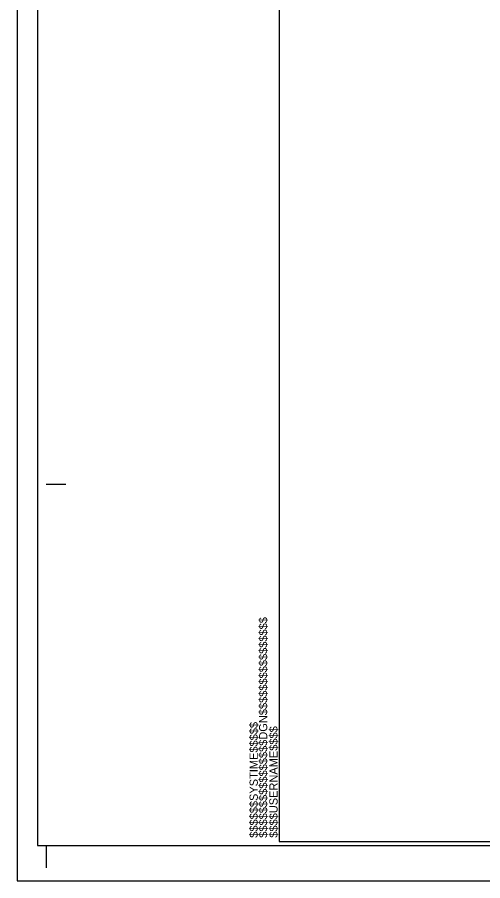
# Model space of a CAD drawing. Extents: x 1542177 to 1542464, y 45134 to 45344.
# Drawn here: x 1542226.01 to 1542249.74, y 45240.62 to 45284.62 of the extents above; entities that cross this region are included whole.
import ezdxf

# ---------------------------------------------------------------- set-up
doc = ezdxf.new("R2010")
doc.units = 0
for name, color, linetype in [('Default', 7, 'Continuous'), ('Sheet Cutting Line CELL', 7, 'Continuous'), ('Sheet Plot Border Inside CELL', 7, 'Continuous'), ('Sheet Plot Border Outside CELL', 7, 'Continuous'), ('Sheet Typical CELL', 7, 'Continuous')]:
    doc.layers.add(name, color=color, linetype=linetype)

# ---------------------------------------------------------------- blocks, each defined once
blk = doc.blocks.new('POINT_DISPLAY')
at = {"layer": 'Default'}
blk.add_line((0, 0), (0, 0), dxfattribs=at)

msp = doc.modelspace()

# ---------------------------------------------------------------- linework, layer by layer
at = {"layer": 'Sheet Cutting Line CELL'}
for p, q in [((1542226.007, 45328.616), (1542226.007, 45240.616)), ((1542226.007, 45240.616), (1542360.727, 45240.616))]:
    msp.add_line(p, q, dxfattribs=at)
at = {"layer": 'Sheet Plot Border Inside CELL'}
msp.add_lwpolyline([(1542360.367, 45326.82), (1542227.047, 45326.82), (1542227.047, 45242.412), (1542360.367, 45242.412)], close=True, dxfattribs=at)
at = {"layer": 'Sheet Plot Border Outside CELL'}
for points in [[(1542360.727, 45328.616), (1542226.007, 45328.616), (1542226.007, 45240.616), (1542360.727, 45240.616)], [(1542360.727, 45328.615), (1542226.007, 45328.615), (1542226.007, 45240.616), (1542360.727, 45240.616)]]:
    msp.add_lwpolyline(points, close=True, dxfattribs=at)
at = {"layer": 'Sheet Typical CELL'}
for p, q in [((1542227.487, 45260.816), (1542228.487, 45260.816)), ((1542239.367, 45242.616), (1542239.367, 45242.616)), ((1542239.367, 45242.616), (1542239.367, 45242.616)), ((1542239.367, 45242.616), (1542239.367, 45242.616)), ((1542239.367, 45242.616), (1542239.367, 45242.616)), ((1542239.367, 45242.616), (1542239.367, 45242.616)), ((1542239.367, 45242.616), (1542239.367, 45242.616)), ((1542227.487, 45242.412), (1542227.487, 45241.267))]:
    msp.add_line(p, q, dxfattribs=at)
msp.add_lwpolyline([(1542359.367, 45326.616), (1542239.367, 45326.616), (1542239.367, 45242.616), (1542359.367, 45242.616)], close=True, dxfattribs=at)
msp.add_lwpolyline([(1542242.367, 45242.616), (1542242.367, 45242.616)], dxfattribs=at)

# ---------------------------------------------------------------- block references
at = {"layer": 'Default', "xscale": 1.3123333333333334, "yscale": 1.3123333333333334}
msp.add_blockref('POINT_DISPLAY', (1542239.367, 45242.616), dxfattribs=at)
msp.add_blockref('POINT_DISPLAY', (1542239.367, 45242.616), dxfattribs=at)
msp.add_blockref('POINT_DISPLAY', (1542239.367, 45242.616), dxfattribs=at)
msp.add_blockref('POINT_DISPLAY', (1542239.367, 45242.616), dxfattribs=at)
msp.add_blockref('POINT_DISPLAY', (1542239.367, 45242.616), dxfattribs=at)
msp.add_blockref('POINT_DISPLAY', (1542239.367, 45242.616), dxfattribs=at)

# ---------------------------------------------------------------- texts
at = {"layer": 'Sheet Typical CELL'}
for s, p in [('$$$$$$$$$$$$$$$$DGN$$$$$$$$$$$$$$$$', (1542238.755, 45242.805)), ('$$$$$$SYSTIME$$$$$', (1542238.271, 45242.805)), ('$$$$USERNAME$$$$', (1542239.281, 45242.806))]:
    msp.add_text(s, height=0.42, rotation=90, dxfattribs=at).set_placement(p)

doc.saveas('drawing.dxf')
